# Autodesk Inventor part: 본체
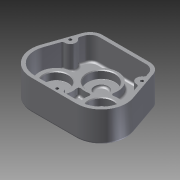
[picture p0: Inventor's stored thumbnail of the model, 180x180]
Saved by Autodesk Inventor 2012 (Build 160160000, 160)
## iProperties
Created: 2014-12
Part Number: 본체
Material: Default
Document SubType Name: Modeling
Designer: Owner
Density: 1 g/cm^3
Mass: 243.559 g
Surface Area: 720.583 cm^2
Volume: 243.559 cm^3
Author: Owner
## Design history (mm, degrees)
sketch "스케치1"
  geometry: L1 (-34.162, 68.527)-(34.162, 68.527); L2 (51.181, 56.389)-(66.565, 11.723); L3 (32.527, -36)-(-32.527, -36); L4 (-66.565, 11.723)-(-51.181, 56.389); L5 (34.162, 63.527)-(-34.162, 63.527); L6 (-46.453, 54.76)-(-61.837, 10.095); L7 (-32.527, -31)-(32.527, -31); L8 (61.837, 10.095)-(46.453, 54.76); C1 r 18 at (0, 32.527); C2 r 7.75 at (-32.527, 0); C3 r 7.75 at (32.527, 0); A1 r 18 centre (-34.162, 50.527) between (-34.162, 68.527) and (-51.181, 56.389); A2 r 18 centre (34.162, 50.527) between (51.181, 56.389) and (34.162, 68.527); A3 r 36 centre (32.527, 0) between (32.527, -36) and (66.565, 11.723); A4 r 36 centre (-32.527, 0) between (-66.565, 11.723) and (-32.527, -36); A5 r 13 centre (-34.162, 50.527) between (-34.162, 63.527) and (-46.453, 54.76); A6 r 31 centre (-32.527, 0) between (-61.837, 10.095) and (-32.527, -31); A7 r 31 centre (32.527, 0) between (32.527, -31) and (61.837, 10.095); A8 r 13 centre (34.162, 50.527) between (46.453, 54.76) and (34.162, 63.527); 4 further points
  constraints: 16 end point, 16 point on circle, 11 centre point, 5 tangent, 4 point on line, 2 coincident, 2 equal radius, 2 horizontal alignment, 2 parallel, 2 vertical alignment, 1 equal length, 1 horizontal, 1 midpoint, 7 other
  dimensions: "d0" = 94 distance of point (-47, 68.527) point (47, 68.527); "d1" = 36 diameter of C1; "d2" = 15.5 diameter of C2; "d3" = 36 distance from line of C3.centre L3; "d4" = 36 distance from line of C1.centre L1; "d5" = 46 distance of C2.centre C1.centre; "d6" = 46 distance of C3.centre C1.centre; "d7" = 90 deg dimension on C1.centre C2.centre C3.centre; "d10" = 18 radius of A1; "d11" = 36 radius of A3; "d12" = 36 radius of A4; "d13" = 5 distance between parallel lines of L2 L8
extrude "돌출1" new body sketch "스케치1" distance "d14" = 44; taper "d15" = 0 deg
extrude "돌출2" cut sketch "스케치1" distance "d16" = 34; taper "d17" = 0 deg
sketch "스케치2"
  geometry: L1 (46.453, 54.76)-(61.837, 10.095) reference; L2 (51.181, 56.389)-(66.565, 11.723) reference; L3 (-34.162, 68.527)-(34.162, 68.527) reference; A1 r 8 centre (51.7, 39.527) between (54.394, 47.06) and (58.461, 35.251); 1 further point
  constraints: 3 point on line, 2 point on circle, 1 centre point
  dimensions: "d18" = 16 diameter of A1; "d19" = 29 distance from line of A1.centre L3
extrude "돌출3" join sketch "스케치2" stored distance "d20" = 41; taper "d21" = 0 deg
hole "구멍1" diameter "d24" = 4.134; stored, may be unused: countersink angle "d28" = 90 deg, drill point angle "d30" = 118 deg; dims "d25" = 20, "d26" = 4, "d27" = 2, "d29" = 23, "d31" = 10, "d32" = 10
sketch "스케치3"
  geometry: L1 (32.527, -31)-(-32.527, -31) reference; L2 (32.527, -36)-(-32.527, -36) reference; A1 r 8 centre (0, -31) between (6.245, -36) and (-6.245, -36); 1 further point
  constraints: 2 point on circle, 2 point on line, 1 centre point, 1 midpoint
  dimensions: "d33" = 16 diameter of A1
extrude "돌출4" join sketch "스케치3" stored distance "d34" = 0; taper "d35" = 0 deg
hole "구멍2" diameter "d38" = 4.134; stored, may be unused: countersink angle "d42" = 90 deg, drill point angle "d44" = 118 deg; dims "d36" = 10, "d37" = 10, "d39" = 20, "d40" = 4, "d41" = 2, "d43" = 23
node "작업 평면1"
sketch "스케치4"
  geometry: L1 (7.75, -44)-(-7.75, -44) reference; L2 (7.75, -34)-(-7.75, -34) reference; L3 (0, -23)-(0, -51); L4 (-24, -23)-(-24, -34); L5 (-20, -44)-(-18.766, -51); L6 (-18.766, -51)-(-15, -51); L7 (-15, -51)-(-15, -44); L8 (-20, -44)-(-7.75, -44); L9 (-24, -23)-(-17.5, -23); L10 (-17.5, -23)-(-17.5, -34); L11 (-24, -34)-(-7.75, -34); L12 (11.723, -44)-(-36, -44) reference; 2 further points
  constraints: 18 end point, 4 parallel, 3 perpendicular, 2 horizontal alignment, 2 point on line, 1 collinear, 1 midpoint, 1 vertical alignment
  dimensions: "d45" = 7 distance from line of L3.end L1; "d46" = 11 distance from line of L3.start L2; "d47" = 48 diameter of L4 L3; "d48" = 35 diameter of L10 L3; "d49" = 100 deg angle of L12 L5; "d50" = 40 diameter of L5.start L3; "d51" = 30 diameter of L7 L3
revolve "회전1" sketch "스케치4" stored, may be unused: angle "d52" = 90 deg
sketch "스케치5"
  geometry: L1 (20, -44)-(-20, -44) reference; L2 (-24, -34)-(24, -34) reference; L3 (-24, -23)-(24, -23) reference; L4 (32.527, -23)-(32.527, -34); L5 (68.527, 0)-(68.527, -44) reference; L6 (56.527, -23)-(56.527, -34); L7 (56.527, -23)-(52.527, -23); L8 (52.527, -23)-(52.527, -34); L9 (52.527, -34)-(56.527, -34); 1 further point
  constraints: 10 end point, 3 horizontal alignment, 3 perpendicular, 2 parallel
  dimensions: "d53" = 36 distance from line of L4.end L5; "d54" = 48 diameter of L6 L4; "d55" = 40 diameter of L8 L4; "d56" = 11 distance of L4.start L4.end
revolve "회전2" sketch "스케치5" stored, may be unused: angle "d57" = 90 deg
fillet "모깎기1" dims "d58" = 3
fillet "모깎기2" dims "d59" = 3
fillet "모깎기3" dims "d60" = 3
hole "구멍3" diameter "d63" = 20; stored, may be unused: countersink angle "d67" = 90 deg, drill point angle "d69" = 0 deg; dims "d64" = 20, "d65" = 4, "d66" = 2, "d68" = 3, "d81" = 10, "d82" = 10
fillet "모깎기4" dims "d70" = 3
fillet "모깎기5" dims "d71" = 0.3, "d72" = 0.1
chamfer "모따기1" distance "d73" = 1; stored, may be unused: second distance "d74" = 2, angle "d75" = 45 deg
sketch "스케치6"
  geometry: L1 (34.162, 68.527)-(-34.162, 68.527) reference; 2 further points
  constraints: 1 vertical alignment, 1 other
  dimensions: "d76" = 30 distance from line of point (0, 38.527) L1
feature "엠보싱1" sketch "스케치6" dims "d0" = 94, "d1" = 36, "d2" = 15.5, "d3" = 36, "d4" = 36, "d5" = 46, "d6" = 46, "d7" = 90 deg, "d10" = 18, "d11" = 36, "d12" = 36, "d13" = 5, "d77" = 1, "d78" = 0
node "솔리드1"
mirror "대칭1"
mirror "대칭2"
other parameters: "d8" = 72, "d9" = 72
